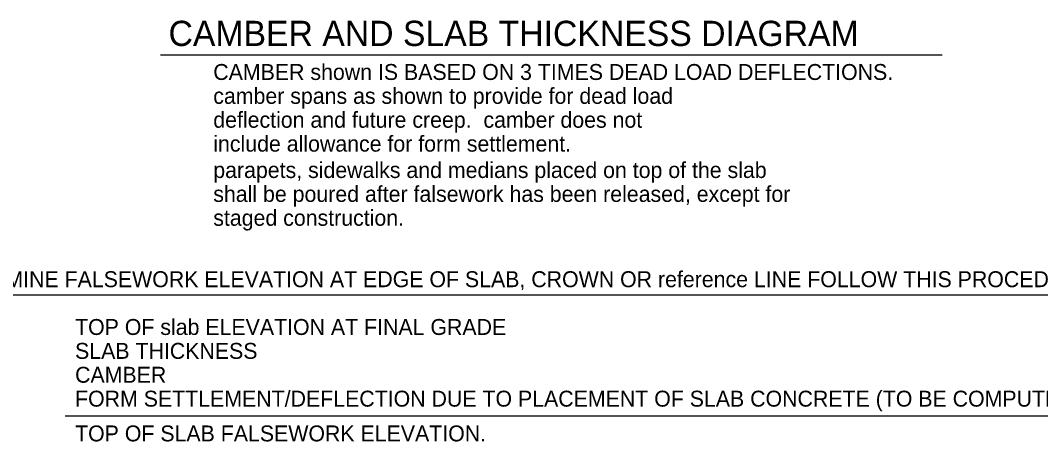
# Model space of a CAD drawing. Extents: x -6.7 to 30.2, y -5.1 to 20.6.
# Drawn here: x 0.72 to 8.72, y 8.8 to 12.1 of the extents above; entities that cross this region are included whole.
import ezdxf

# ---------------------------------------------------------------- set-up
doc = ezdxf.new("R2010")
doc.units = 0
doc.layers.add('Level 4', color=7, linetype='Continuous')

msp = doc.modelspace()

# ---------------------------------------------------------------- linework, layer by layer
at = {"layer": 'Level 4'}
for p, q in [((1.8212, 11.8347), (7.9506, 11.8347)), ((-0.2398, 9.9505), (10.597, 9.9505)), ((1.0732, 9.0004), (12.2057, 9.0004))]:
    msp.add_line(p, q, dxfattribs=at)

# ---------------------------------------------------------------- texts
for s, height, p in [('CAMBER AND SLAB THICKNESS DIAGRAM', 0.197917, (1.8847, 11.9034)), ('CAMBER shown IS BASED ON 3 TIMES DEAD LOAD DEFLECTIONS.', 0.125, (2.2355, 11.6368)), ('camber spans as shown to provide for dead load', 0.125, (2.2355, 11.4493)), ('deflection and future creep.  camber does not', 0.125, (2.2355, 11.2618)), ('include allowance for form settlement.', 0.125, (2.2355, 11.0743)), ('parapets, sidewalks and medians placed on top of the slab ', 0.125, (2.2355, 10.8674)), ('shall be poured after falsework has been released, except for ', 0.125, (2.2355, 10.6799)), ('staged construction.', 0.125, (2.2355, 10.4924)), ('TO DETERMINE FALSEWORK ELEVATION AT EDGE OF SLAB, CROWN OR reference LINE FOLLOW THIS PROCEDURE:', 0.125, (-0.2398, 10.0106)), ('TOP OF slab ELEVATION AT FINAL GRADE', 0.125, (1.1517, 9.6356)), ('SLAB THICKNESS', 0.125, (1.1517, 9.4481)), ('CAMBER', 0.125, (1.1517, 9.2606)), ('FORM SETTLEMENT/DEFLECTION DUE TO PLACEMENT OF SLAB CONCRETE (TO BE COMPUTED BY THE CONTRACTOR)', 0.125, (1.1517, 9.0731)), ('TOP OF SLAB FALSEWORK ELEVATION.', 0.125, (1.1517, 8.8003))]:
    msp.add_text(s, height=height, dxfattribs=at).set_placement(p)

doc.saveas('drawing.dxf')
